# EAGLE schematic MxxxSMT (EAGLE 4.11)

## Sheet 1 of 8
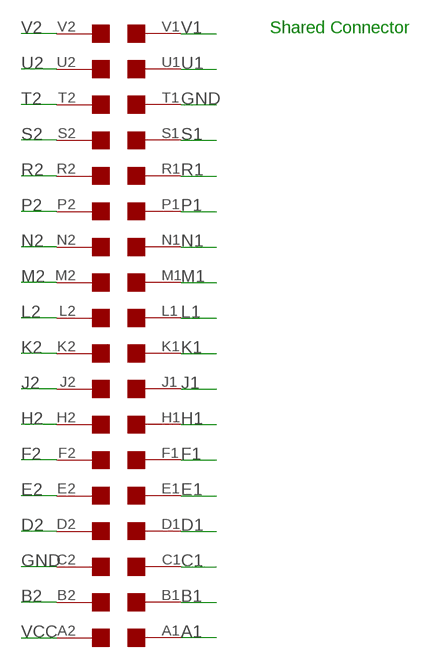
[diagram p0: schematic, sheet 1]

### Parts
U$1  EDGE-2  [EDGE-CON2]

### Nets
A1: U$1.A1 ; also sheet 2,3,4,5,6,7,8
B1: U$1.B1 ; also sheet 2,3,4,5,6,7,8
B2: U$1.B2
C1: U$1.C1 ; also sheet 2,3,4,5,6,7,8
D1: U$1.D1 ; also sheet 2,3,4,5,6,7,8
D2: U$1.D2 ; also sheet 2,3,4,5,6,7,8
E1: U$1.E1 ; also sheet 2,3,4,5,7,8
E2: U$1.E2 ; also sheet 2,3,4,5,6,7,8
F1: U$1.F1 ; also sheet 2,3,4,5,6,7,8
F2: U$1.F2 ; also sheet 2,3,4,5,6,7,8
GND [Power]: U$1.C2 U$1.T1 ; also sheet 2,3,4,5,6,7,8
H1: U$1.H1 ; also sheet 2,3,4,5,6,7,8
H2: U$1.H2 ; also sheet 2,3,4,5,6,7,8
J1: U$1.J1 ; also sheet 2,3,4,5,6,7,8
J2: U$1.J2 ; also sheet 2,3,4,5,6,7,8
K1: U$1.K1 ; also sheet 2,3,4,5,6,7,8
K2: U$1.K2 ; also sheet 2,3,4,5,6,7,8
L1: U$1.L1 ; also sheet 2,3,4,5,7,8
L2: U$1.L2 ; also sheet 2,3,4,5,6,7,8
M1: U$1.M1 ; also sheet 2,3,4,5,6,7,8
M2: U$1.M2 ; also sheet 2,3,4,5,6,7,8
N1: U$1.N1 ; also sheet 2,3,4,5,6,7,8
N2: U$1.N2 ; also sheet 2,3,4,5,6,7,8
P1: U$1.P1 ; also sheet 2,3,4,5,6,7,8
P2: U$1.P2 ; also sheet 2,3,4,5,6,7,8
R1: U$1.R1 ; also sheet 2,3,4,5,6,7,8
R2: U$1.R2 ; also sheet 2,3,4,5,6,7,8
S1: U$1.S1 ; also sheet 2,3,4,5,7,8
S2: U$1.S2 ; also sheet 2,3,4,5,6,7,8
T2: U$1.T2 ; also sheet 2,3,4,5,6,7,8
U1: U$1.U1 ; also sheet 2,3,4,7,8
U2: U$1.U2 ; also sheet 2,3,4,5,6,7,8
V1: U$1.V1 ; also sheet 2,3,4,7,8
V2: U$1.V2 ; also sheet 2,3,4,5,6,7,8
VCC [Power]: U$1.A2 ; also sheet 2,3,4,5,6,7,8

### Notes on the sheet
- Shared Connector

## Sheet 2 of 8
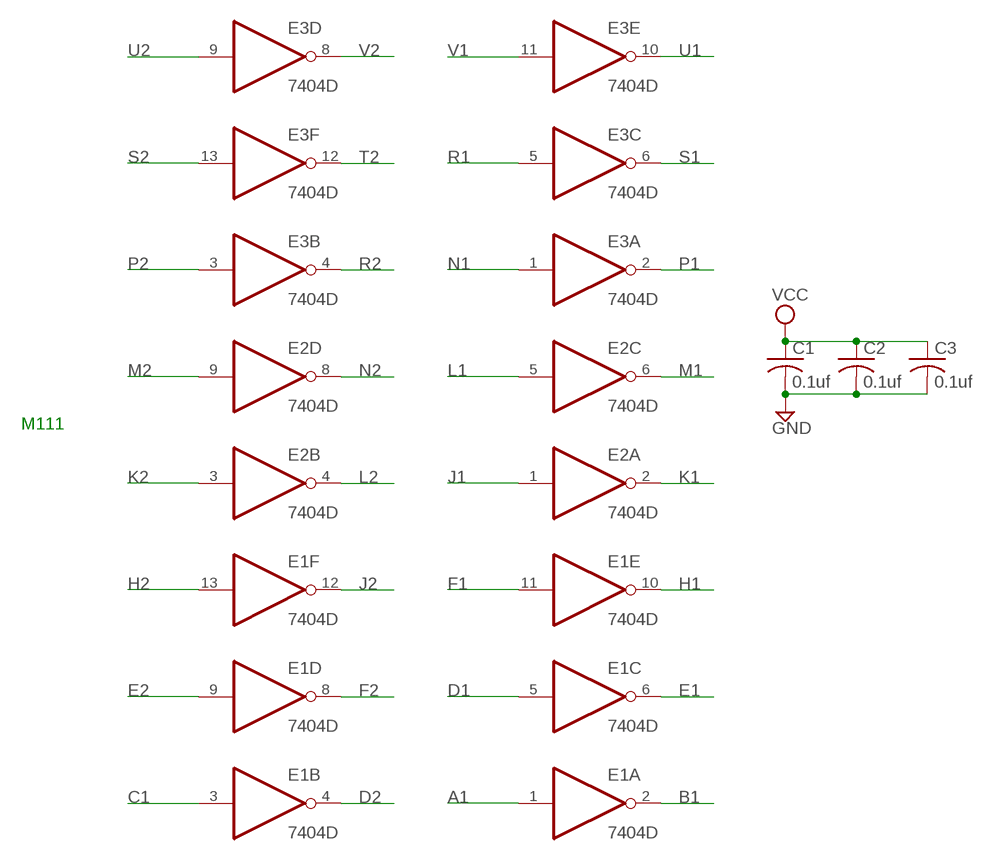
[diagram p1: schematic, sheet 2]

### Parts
C1  0.1uf  C-US025-025X050  [C025-025X050]
C2  0.1uf  C-US025-025X050  [C025-025X050]
C3  0.1uf  C-US050-025X075  [C050-025X075]
E1  7404D  [SO14]
E2  7404D  [SO14]
E3  7404D  [SO14]

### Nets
A1: E1.1(A:I) ; also sheet 1,3,4,5,6,7,8
B1: E1.2(A:O) ; also sheet 1,3,4,5,6,7,8
C1: E1.3(B:I) ; also sheet 1,3,4,5,6,7,8
D1: E1.5(C:I) ; also sheet 1,3,4,5,6,7,8
D2: E1.4(B:O) ; also sheet 1,3,4,5,6,7,8
E1: E1.6(C:O) ; also sheet 1,3,4,5,7,8
E2: E1.9(D:I) ; also sheet 1,3,4,5,6,7,8
F1: E1.11(E:I) ; also sheet 1,3,4,5,6,7,8
F2: E1.8(D:O) ; also sheet 1,3,4,5,6,7,8
GND [Power]: C1.2 C2.2 C3.2 ; also sheet 1,3,4,5,6,7,8
H1: E1.10(E:O) ; also sheet 1,3,4,5,6,7,8
H2: E1.13(F:I) ; also sheet 1,3,4,5,6,7,8
J1: E2.1(A:I) ; also sheet 1,3,4,5,6,7,8
J2: E1.12(F:O) ; also sheet 1,3,4,5,6,7,8
K1: E2.2(A:O) ; also sheet 1,3,4,5,6,7,8
K2: E2.3(B:I) ; also sheet 1,3,4,5,6,7,8
L1: E2.5(C:I) ; also sheet 1,3,4,5,7,8
L2: E2.4(B:O) ; also sheet 1,3,4,5,6,7,8
M1: E2.6(C:O) ; also sheet 1,3,4,5,6,7,8
M2: E2.9(D:I) ; also sheet 1,3,4,5,6,7,8
N1: E3.1(A:I) ; also sheet 1,3,4,5,6,7,8
N2: E2.8(D:O) ; also sheet 1,3,4,5,6,7,8
P1: E3.2(A:O) ; also sheet 1,3,4,5,6,7,8
P2: E3.3(B:I) ; also sheet 1,3,4,5,6,7,8
R1: E3.5(C:I) ; also sheet 1,3,4,5,6,7,8
R2: E3.4(B:O) ; also sheet 1,3,4,5,6,7,8
S1: E3.6(C:O) ; also sheet 1,3,4,5,7,8
S2: E3.13(F:I) ; also sheet 1,3,4,5,6,7,8
T2: E3.12(F:O) ; also sheet 1,3,4,5,6,7,8
U1: E3.10(E:O) ; also sheet 1,3,4,7,8
U2: E3.9(D:I) ; also sheet 1,3,4,5,6,7,8
V1: E3.11(E:I) ; also sheet 1,3,4,7,8
V2: E3.8(D:O) ; also sheet 1,3,4,5,6,7,8
VCC [Power]: C1.1 C2.1 C3.1 ; also sheet 1,3,4,5,6,7,8
Unconnected: E2.10(E:O) E2.11(E:I) E2.12(F:O) E2.13(F:I)

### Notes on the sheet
- M111

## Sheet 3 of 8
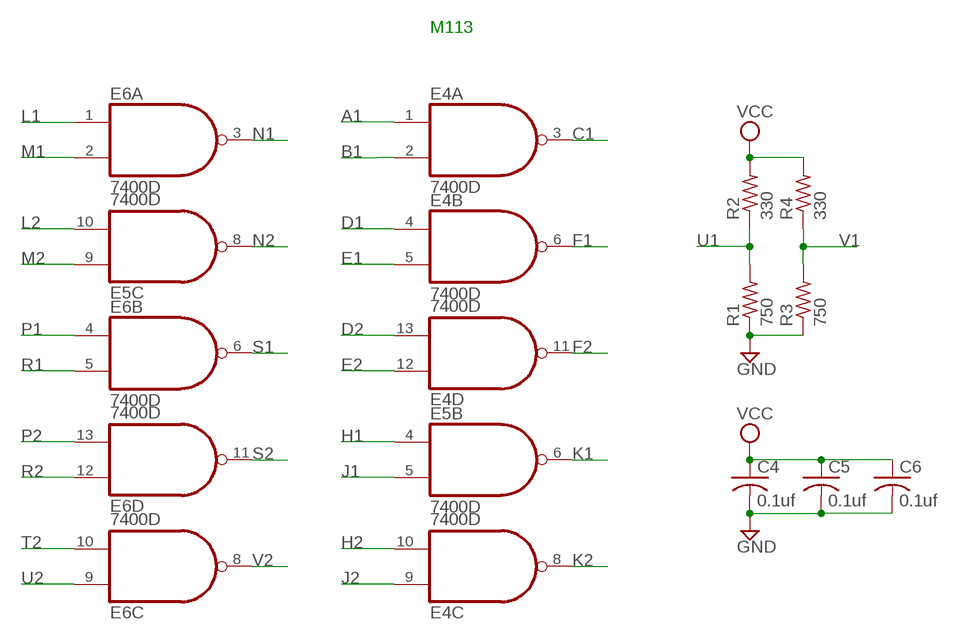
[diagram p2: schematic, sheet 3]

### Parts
C4  0.1uf  C-US025-025X050  [C025-025X050]
C5  0.1uf  C-US025-025X050  [C025-025X050]
C6  0.1uf  C-US025-025X050  [C025-025X050]
E4  7400D  [SO14]
E5  7400D  [SO14]
E6  7400D  [SO14]
R1  750  R-US_0207/10  [0207/10]
R2  330  R-US_0207/10  [0207/10]
R3  750  R-US_0207/10  [0207/10]
R4  330  R-US_0207/10  [0207/10]

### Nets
A1: E4.1(A:I0) ; also sheet 1,2,4,5,6,7,8
B1: E4.2(A:I1) ; also sheet 1,2,4,5,6,7,8
C1: E4.3(A:O) ; also sheet 1,2,4,5,6,7,8
D1: E4.4(B:I0) ; also sheet 1,2,4,5,6,7,8
D2: E4.13(D:I1) ; also sheet 1,2,4,5,6,7,8
E1: E4.5(B:I1) ; also sheet 1,2,4,5,7,8
E2: E4.12(D:I0) ; also sheet 1,2,4,5,6,7,8
F1: E4.6(B:O) ; also sheet 1,2,4,5,6,7,8
F2: E4.11(D:O) ; also sheet 1,2,4,5,6,7,8
GND [Power]: C4.2 C5.2 C6.2 R1.1 R3.1 ; also sheet 1,2,4,5,6,7,8
H1: E5.4(B:I0) ; also sheet 1,2,4,5,6,7,8
H2: E4.10(C:I1) ; also sheet 1,2,4,5,6,7,8
J1: E5.5(B:I1) ; also sheet 1,2,4,5,6,7,8
J2: E4.9(C:I0) ; also sheet 1,2,4,5,6,7,8
K1: E5.6(B:O) ; also sheet 1,2,4,5,6,7,8
K2: E4.8(C:O) ; also sheet 1,2,4,5,6,7,8
L1: E6.1(A:I0) ; also sheet 1,2,4,5,7,8
L2: E5.10(C:I1) ; also sheet 1,2,4,5,6,7,8
M1: E6.2(A:I1) ; also sheet 1,2,4,5,6,7,8
M2: E5.9(C:I0) ; also sheet 1,2,4,5,6,7,8
N1: E6.3(A:O) ; also sheet 1,2,4,5,6,7,8
N2: E5.8(C:O) ; also sheet 1,2,4,5,6,7,8
P1: E6.4(B:I0) ; also sheet 1,2,4,5,6,7,8
P2: E6.13(D:I1) ; also sheet 1,2,4,5,6,7,8
R1: E6.5(B:I1) ; also sheet 1,2,4,5,6,7,8
R2: E6.12(D:I0) ; also sheet 1,2,4,5,6,7,8
S1: E6.6(B:O) ; also sheet 1,2,4,5,7,8
S2: E6.11(D:O) ; also sheet 1,2,4,5,6,7,8
T2: E6.10(C:I1) ; also sheet 1,2,4,5,6,7,8
U1: R1.2 R2.1 ; also sheet 1,2,4,7,8
U2: E6.9(C:I0) ; also sheet 1,2,4,5,6,7,8
V1: R3.2 R4.1 ; also sheet 1,2,4,7,8
V2: E6.8(C:O) ; also sheet 1,2,4,5,6,7,8
VCC [Power]: C4.1 C5.1 C6.1 R2.2 R4.2 ; also sheet 1,2,4,5,6,7,8
Unconnected: E5.1(A:I0) E5.2(A:I1) E5.3(A:O) E5.11(D:O) E5.12(D:I0) E5.13(D:I1)

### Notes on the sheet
- M113

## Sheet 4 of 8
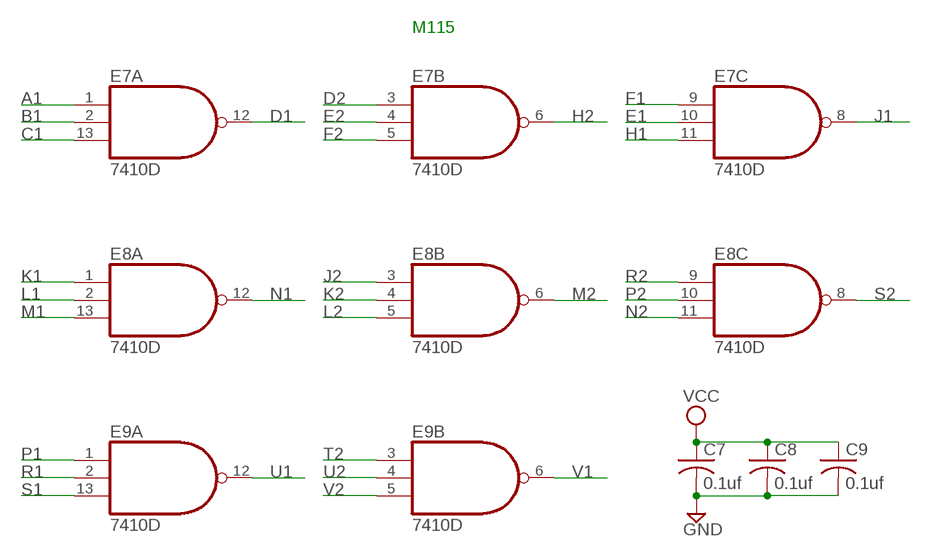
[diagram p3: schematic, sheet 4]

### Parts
C7  0.1uf  C-US025-025X050  [C025-025X050]
C8  0.1uf  C-US025-025X050  [C025-025X050]
C9  0.1uf  C-US025-025X050  [C025-025X050]
E7  7410D  [SO14]
E8  7410D  [SO14]
E9  7410D  [SO14]

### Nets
A1: E7.1(A:I0) ; also sheet 1,2,3,5,6,7,8
B1: E7.2(A:I1) ; also sheet 1,2,3,5,6,7,8
C1: E7.13(A:I2) ; also sheet 1,2,3,5,6,7,8
D1: E7.12(A:O) ; also sheet 1,2,3,5,6,7,8
D2: E7.3(B:I0) ; also sheet 1,2,3,5,6,7,8
E1: E7.10(C:I1) ; also sheet 1,2,3,5,7,8
E2: E7.4(B:I1) ; also sheet 1,2,3,5,6,7,8
F1: E7.9(C:I0) ; also sheet 1,2,3,5,6,7,8
F2: E7.5(B:I2) ; also sheet 1,2,3,5,6,7,8
GND [Power]: C7.2 C8.2 C9.2 ; also sheet 1,2,3,5,6,7,8
H1: E7.11(C:I2) ; also sheet 1,2,3,5,6,7,8
H2: E7.6(B:O) ; also sheet 1,2,3,5,6,7,8
J1: E7.8(C:O) ; also sheet 1,2,3,5,6,7,8
J2: E8.3(B:I0) ; also sheet 1,2,3,5,6,7,8
K1: E8.1(A:I0) ; also sheet 1,2,3,5,6,7,8
K2: E8.4(B:I1) ; also sheet 1,2,3,5,6,7,8
L1: E8.2(A:I1) ; also sheet 1,2,3,5,7,8
L2: E8.5(B:I2) ; also sheet 1,2,3,5,6,7,8
M1: E8.13(A:I2) ; also sheet 1,2,3,5,6,7,8
M2: E8.6(B:O) ; also sheet 1,2,3,5,6,7,8
N1: E8.12(A:O) ; also sheet 1,2,3,5,6,7,8
N2: E8.11(C:I2) ; also sheet 1,2,3,5,6,7,8
P1: E9.1(A:I0) ; also sheet 1,2,3,5,6,7,8
P2: E8.10(C:I1) ; also sheet 1,2,3,5,6,7,8
R1: E9.2(A:I1) ; also sheet 1,2,3,5,6,7,8
R2: E8.9(C:I0) ; also sheet 1,2,3,5,6,7,8
S1: E9.13(A:I2) ; also sheet 1,2,3,5,7,8
S2: E8.8(C:O) ; also sheet 1,2,3,5,6,7,8
T2: E9.3(B:I0) ; also sheet 1,2,3,5,6,7,8
U1: E9.12(A:O) ; also sheet 1,2,3,7,8
U2: E9.4(B:I1) ; also sheet 1,2,3,5,6,7,8
V1: E9.6(B:O) ; also sheet 1,2,3,7,8
V2: E9.5(B:I2) ; also sheet 1,2,3,5,6,7,8
VCC [Power]: C7.1 C8.1 C9.1 ; also sheet 1,2,3,5,6,7,8
Unconnected: E9.8(C:O) E9.9(C:I0) E9.10(C:I1) E9.11(C:I2)

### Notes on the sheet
- M115

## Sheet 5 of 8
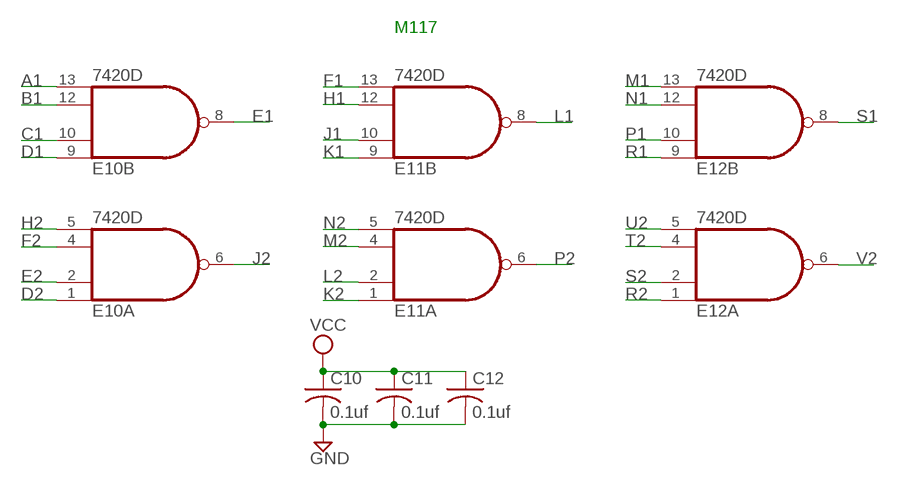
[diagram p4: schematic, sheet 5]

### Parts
C10  0.1uf  C-US025-025X050  [C025-025X050]
C11  0.1uf  C-US025-025X050  [C025-025X050]
C12  0.1uf  C-US025-025X050  [C025-025X050]
E10  7420D  74S20D  [SO14]
E11  7420D  74S20D  [SO14]
E12  7420D  74S20D  [SO14]

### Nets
A1: E10.13(B:I3) ; also sheet 1,2,3,4,6,7,8
B1: E10.12(B:I2) ; also sheet 1,2,3,4,6,7,8
C1: E10.10(B:I1) ; also sheet 1,2,3,4,6,7,8
D1: E10.9(B:I0) ; also sheet 1,2,3,4,6,7,8
D2: E10.1(A:I0) ; also sheet 1,2,3,4,6,7,8
E1: E10.8(B:O) ; also sheet 1,2,3,4,7,8
E2: E10.2(A:I1) ; also sheet 1,2,3,4,6,7,8
F1: E11.13(B:I3) ; also sheet 1,2,3,4,6,7,8
F2: E10.4(A:I2) ; also sheet 1,2,3,4,6,7,8
GND [Power]: C10.2 C11.2 C12.2 ; also sheet 1,2,3,4,6,7,8
H1: E11.12(B:I2) ; also sheet 1,2,3,4,6,7,8
H2: E10.5(A:I3) ; also sheet 1,2,3,4,6,7,8
J1: E11.10(B:I1) ; also sheet 1,2,3,4,6,7,8
J2: E10.6(A:O) ; also sheet 1,2,3,4,6,7,8
K1: E11.9(B:I0) ; also sheet 1,2,3,4,6,7,8
K2: E11.1(A:I0) ; also sheet 1,2,3,4,6,7,8
L1: E11.8(B:O) ; also sheet 1,2,3,4,7,8
L2: E11.2(A:I1) ; also sheet 1,2,3,4,6,7,8
M1: E12.13(B:I3) ; also sheet 1,2,3,4,6,7,8
M2: E11.4(A:I2) ; also sheet 1,2,3,4,6,7,8
N1: E12.12(B:I2) ; also sheet 1,2,3,4,6,7,8
N2: E11.5(A:I3) ; also sheet 1,2,3,4,6,7,8
P1: E12.10(B:I1) ; also sheet 1,2,3,4,6,7,8
P2: E11.6(A:O) ; also sheet 1,2,3,4,6,7,8
R1: E12.9(B:I0) ; also sheet 1,2,3,4,6,7,8
R2: E12.1(A:I0) ; also sheet 1,2,3,4,6,7,8
S1: E12.8(B:O) ; also sheet 1,2,3,4,7,8
S2: E12.2(A:I1) ; also sheet 1,2,3,4,6,7,8
T2: E12.4(A:I2) ; also sheet 1,2,3,4,6,7,8
U2: E12.5(A:I3) ; also sheet 1,2,3,4,6,7,8
V2: E12.6(A:O) ; also sheet 1,2,3,4,6,7,8
VCC [Power]: C10.1 C11.1 C12.1 ; also sheet 1,2,3,4,6,7,8

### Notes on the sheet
- M117

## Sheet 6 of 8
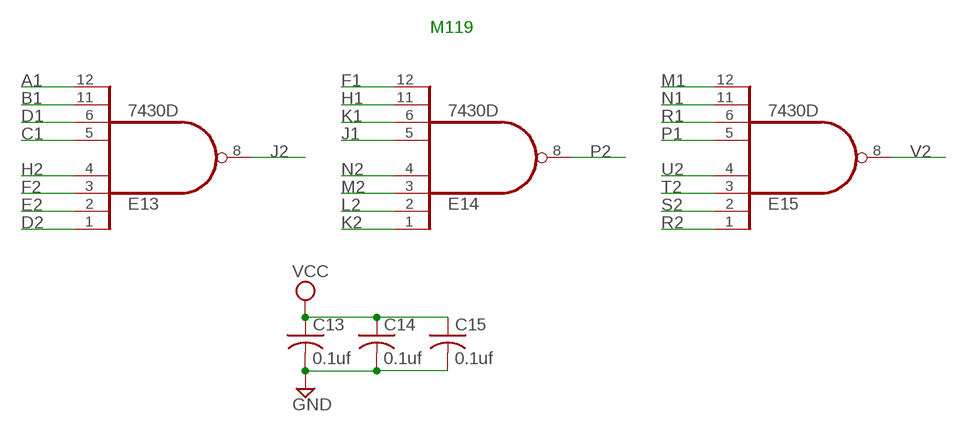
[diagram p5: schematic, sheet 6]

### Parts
C13  0.1uf  C-US025-025X050  [C025-025X050]
C14  0.1uf  C-US025-025X050  [C025-025X050]
C15  0.1uf  C-US025-025X050  [C025-025X050]
E13  7430D  [SO14]
E14  7430D  [SO14]
E15  7430D  [SO14]

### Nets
A1: E13.12(I7) ; also sheet 1,2,3,4,5,7,8
B1: E13.11(I6) ; also sheet 1,2,3,4,5,7,8
C1: E13.5(I4) ; also sheet 1,2,3,4,5,7,8
D1: E13.6(I5) ; also sheet 1,2,3,4,5,7,8
D2: E13.1(I0) ; also sheet 1,2,3,4,5,7,8
E2: E13.2(I1) ; also sheet 1,2,3,4,5,7,8
F1: E14.12(I7) ; also sheet 1,2,3,4,5,7,8
F2: E13.3(I2) ; also sheet 1,2,3,4,5,7,8
GND [Power]: C13.2 C14.2 C15.2 ; also sheet 1,2,3,4,5,7,8
H1: E14.11(I6) ; also sheet 1,2,3,4,5,7,8
H2: E13.4(I3) ; also sheet 1,2,3,4,5,7,8
J1: E14.5(I4) ; also sheet 1,2,3,4,5,7,8
J2: E13.8(O) ; also sheet 1,2,3,4,5,7,8
K1: E14.6(I5) ; also sheet 1,2,3,4,5,7,8
K2: E14.1(I0) ; also sheet 1,2,3,4,5,7,8
L2: E14.2(I1) ; also sheet 1,2,3,4,5,7,8
M1: E15.12(I7) ; also sheet 1,2,3,4,5,7,8
M2: E14.3(I2) ; also sheet 1,2,3,4,5,7,8
N1: E15.11(I6) ; also sheet 1,2,3,4,5,7,8
N2: E14.4(I3) ; also sheet 1,2,3,4,5,7,8
P1: E15.5(I4) ; also sheet 1,2,3,4,5,7,8
P2: E14.8(O) ; also sheet 1,2,3,4,5,7,8
R1: E15.6(I5) ; also sheet 1,2,3,4,5,7,8
R2: E15.1(I0) ; also sheet 1,2,3,4,5,7,8
S2: E15.2(I1) ; also sheet 1,2,3,4,5,7,8
T2: E15.3(I2) ; also sheet 1,2,3,4,5,7,8
U2: E15.4(I3) ; also sheet 1,2,3,4,5,7,8
V2: E15.8(O) ; also sheet 1,2,3,4,5,7,8
VCC [Power]: C13.1 C14.1 C15.1 ; also sheet 1,2,3,4,5,7,8

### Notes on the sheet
- M119

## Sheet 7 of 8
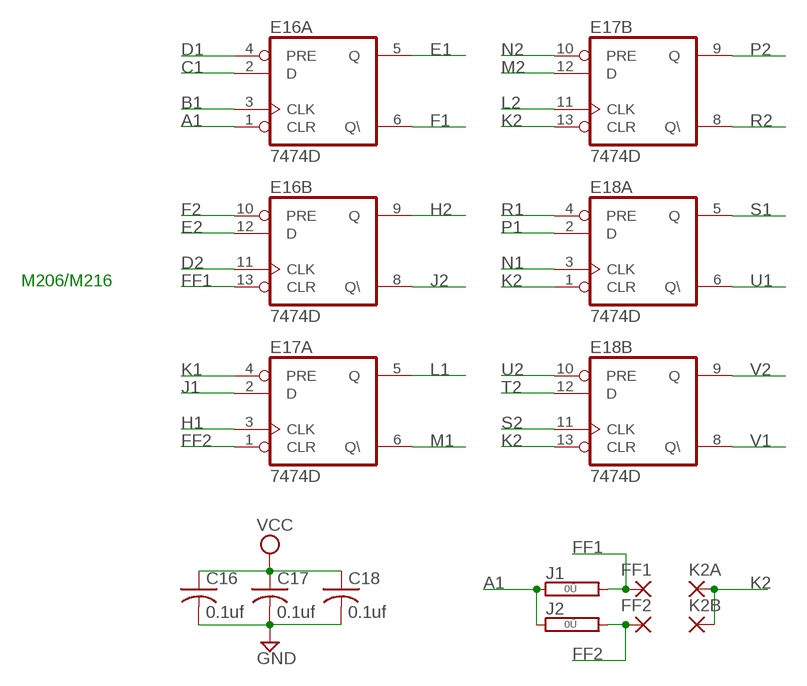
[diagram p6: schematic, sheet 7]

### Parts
C16  0.1uf  C-US025-025X050  [C025-025X050]
C17  0.1uf  C-US025-025X050  [C025-025X050]
C18  0.1uf  C-US025-025X050  [C025-025X050]
E16  7474D  74S74D  [SO14]
E17  7474D  74S74D  [SO14]
E18  7474D  74S74D  [SO14]
FF1  1,6/0,8  [1,6/0,8]
FF2  1,6/0,8  [1,6/0,8]
J1  0R  [0R/10]
J2  0R  [0R/10]
K2A  1,6/0,8  [1,6/0,8]
K2B  1,6/0,8  [1,6/0,8]

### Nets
A1: E16.1(A:CLR) J1.1 J2.1 ; also sheet 1,2,3,4,5,6,8
B1: E16.3(A:CLK) ; also sheet 1,2,3,4,5,6,8
C1: E16.2(A:D) ; also sheet 1,2,3,4,5,6,8
D1: E16.4(A:PRE) ; also sheet 1,2,3,4,5,6,8
D2: E16.11(B:CLK) ; also sheet 1,2,3,4,5,6,8
E1: E16.5(A:Q) ; also sheet 1,2,3,4,5,8
E2: E16.12(B:D) ; also sheet 1,2,3,4,5,6,8
F1: E16.6(A:Q\) ; also sheet 1,2,3,4,5,6,8
F2: E16.10(B:PRE) ; also sheet 1,2,3,4,5,6,8
FF1: E16.13(B:CLR) FF1.1(P) J1.2 ; also sheet 8
FF2: E17.1(A:CLR) FF2.1(P) J2.2 ; also sheet 8
GND [Power]: C16.2 C17.2 C18.2 ; also sheet 1,2,3,4,5,6,8
H1: E17.3(A:CLK) ; also sheet 1,2,3,4,5,6,8
H2: E16.9(B:Q) ; also sheet 1,2,3,4,5,6,8
J1: E17.2(A:D) ; also sheet 1,2,3,4,5,6,8
J2: E16.8(B:Q\) ; also sheet 1,2,3,4,5,6,8
K1: E17.4(A:PRE) ; also sheet 1,2,3,4,5,6,8
K2: E17.13(B:CLR) E18.1(A:CLR) E18.13(B:CLR) K2A.1(P) K2B.1(P) ; also sheet 1,2,3,4,5,6,8
L1: E17.5(A:Q) ; also sheet 1,2,3,4,5,8
L2: E17.11(B:CLK) ; also sheet 1,2,3,4,5,6,8
M1: E17.6(A:Q\) ; also sheet 1,2,3,4,5,6,8
M2: E17.12(B:D) ; also sheet 1,2,3,4,5,6,8
N1: E18.3(A:CLK) ; also sheet 1,2,3,4,5,6,8
N2: E17.10(B:PRE) ; also sheet 1,2,3,4,5,6,8
P1: E18.2(A:D) ; also sheet 1,2,3,4,5,6,8
P2: E17.9(B:Q) ; also sheet 1,2,3,4,5,6,8
R1: E18.4(A:PRE) ; also sheet 1,2,3,4,5,6,8
R2: E17.8(B:Q\) ; also sheet 1,2,3,4,5,6,8
S1: E18.5(A:Q) ; also sheet 1,2,3,4,5,8
S2: E18.11(B:CLK) ; also sheet 1,2,3,4,5,6,8
T2: E18.12(B:D) ; also sheet 1,2,3,4,5,6,8
U1: E18.6(A:Q\) ; also sheet 1,2,3,4,8
U2: E18.10(B:PRE) ; also sheet 1,2,3,4,5,6,8
V1: E18.8(B:Q\) ; also sheet 1,2,3,4,8
V2: E18.9(B:Q) ; also sheet 1,2,3,4,5,6,8
VCC [Power]: C16.1 C17.1 C18.1 ; also sheet 1,2,3,4,5,6,8

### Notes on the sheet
- M206/M216

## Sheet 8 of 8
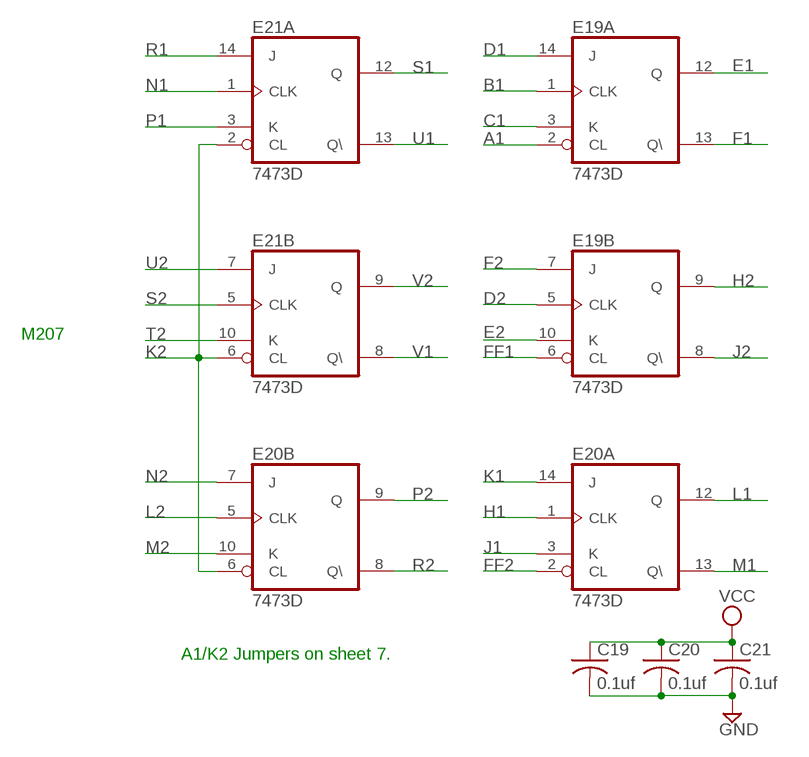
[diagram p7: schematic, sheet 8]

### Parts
C19  0.1uf  C-US025-025X050  [C025-025X050]
C20  0.1uf  C-US025-025X050  [C025-025X050]
C21  0.1uf  C-US025-025X050  [C025-025X050]
E19  7473D  74LS73D  [SO14]
E20  7473D  74LS73D  [SO14]
E21  7473D  74LS73D  [SO14]

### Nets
A1: E19.2(A:CL) ; also sheet 1,2,3,4,5,6,7
B1: E19.1(A:CLK) ; also sheet 1,2,3,4,5,6,7
C1: E19.3(A:K) ; also sheet 1,2,3,4,5,6,7
D1: E19.14(A:J) ; also sheet 1,2,3,4,5,6,7
D2: E19.5(B:CLK) ; also sheet 1,2,3,4,5,6,7
E1: E19.12(A:Q) ; also sheet 1,2,3,4,5,7
E2: E19.10(B:K) ; also sheet 1,2,3,4,5,6,7
F1: E19.13(A:Q\) ; also sheet 1,2,3,4,5,6,7
F2: E19.7(B:J) ; also sheet 1,2,3,4,5,6,7
FF1: E19.6(B:CL) ; also sheet 7
FF2: E20.2(A:CL) ; also sheet 7
GND [Power]: C19.2 C20.2 C21.2 ; also sheet 1,2,3,4,5,6,7
H1: E20.1(A:CLK) ; also sheet 1,2,3,4,5,6,7
H2: E19.9(B:Q) ; also sheet 1,2,3,4,5,6,7
J1: E20.3(A:K) ; also sheet 1,2,3,4,5,6,7
J2: E19.8(B:Q\) ; also sheet 1,2,3,4,5,6,7
K1: E20.14(A:J) ; also sheet 1,2,3,4,5,6,7
K2: E20.6(B:CL) E21.2(A:CL) E21.6(B:CL) ; also sheet 1,2,3,4,5,6,7
L1: E20.12(A:Q) ; also sheet 1,2,3,4,5,7
L2: E20.5(B:CLK) ; also sheet 1,2,3,4,5,6,7
M1: E20.13(A:Q\) ; also sheet 1,2,3,4,5,6,7
M2: E20.10(B:K) ; also sheet 1,2,3,4,5,6,7
N1: E21.1(A:CLK) ; also sheet 1,2,3,4,5,6,7
N2: E20.7(B:J) ; also sheet 1,2,3,4,5,6,7
P1: E21.3(A:K) ; also sheet 1,2,3,4,5,6,7
P2: E20.9(B:Q) ; also sheet 1,2,3,4,5,6,7
R1: E21.14(A:J) ; also sheet 1,2,3,4,5,6,7
R2: E20.8(B:Q\) ; also sheet 1,2,3,4,5,6,7
S1: E21.12(A:Q) ; also sheet 1,2,3,4,5,7
S2: E21.5(B:CLK) ; also sheet 1,2,3,4,5,6,7
T2: E21.10(B:K) ; also sheet 1,2,3,4,5,6,7
U1: E21.13(A:Q\) ; also sheet 1,2,3,4,7
U2: E21.7(B:J) ; also sheet 1,2,3,4,5,6,7
V1: E21.8(B:Q\) ; also sheet 1,2,3,4,7
V2: E21.9(B:Q) ; also sheet 1,2,3,4,5,6,7
VCC [Power]: C19.1 C20.1 C21.1 ; also sheet 1,2,3,4,5,6,7

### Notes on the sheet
- M207
- A1/K2 Jumpers on sheet 7.

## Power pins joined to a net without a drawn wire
GND: E1.7(P:GND) E2.7(P:GND) E3.7(P:GND) E4.7(P:GND) E5.7(P:GND) E6.7(P:GND) E7.7(P:GND) E8.7(P:GND) E9.7(P:GND) E10.7(P:GND) E11.7(P:GND) E12.7(P:GND) E13.7(GND) E14.7(GND) E15.7(GND) E16.7(P:GND) E17.7(P:GND) E18.7(P:GND) E19.11(P:GND) E20.11(P:GND) E21.11(P:GND)
VCC: E1.14(P:VCC) E2.14(P:VCC) E3.14(P:VCC) E4.14(P:VCC) E5.14(P:VCC) E6.14(P:VCC) E7.14(P:VCC) E8.14(P:VCC) E9.14(P:VCC) E10.14(P:VCC) E11.14(P:VCC) E12.14(P:VCC) E13.14(VCC) E14.14(VCC) E15.14(VCC) E16.14(P:VCC) E17.14(P:VCC) E18.14(P:VCC) E19.4(P:VCC) E20.4(P:VCC) E21.4(P:VCC)

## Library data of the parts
C1-C21 = rcl:C-US: CAPACITOR, American symbol
E1-E3 = 74xx-us:74*04: Hex INVERTER
E4-E6 = 74xx-us:74*00: Quad 2-input NAND gate
E7-E9 = 74xx-us:74*10: Triple 3-input NAND gate
E10-E12 = 74xx-us:74*20: Dual 4-input NAND gate
E13-E15 = 74xx-us:74*30: 8-input NAND gate
E16-E18 = 74xx-us:74*74: Dual D type positive edge triggered FLIP FLOP, preset and clear
E19-E21 = 74xx-us:74*73: Dual J-K FLIP FLOP, clear
FF1 FF2 K2A K2B = wirepad:1,6/0,8: THROUGH-HOLE PAD
J1 J2 = jumper:0R: Bridge 0R 10mm
R1-R4 = rcl:R-US_: RESISTOR, American symbol
U$1 = dec-con:EDGE-2: Double-Sided DEC edge connector.

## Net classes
1 Power: width 0.381 mm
